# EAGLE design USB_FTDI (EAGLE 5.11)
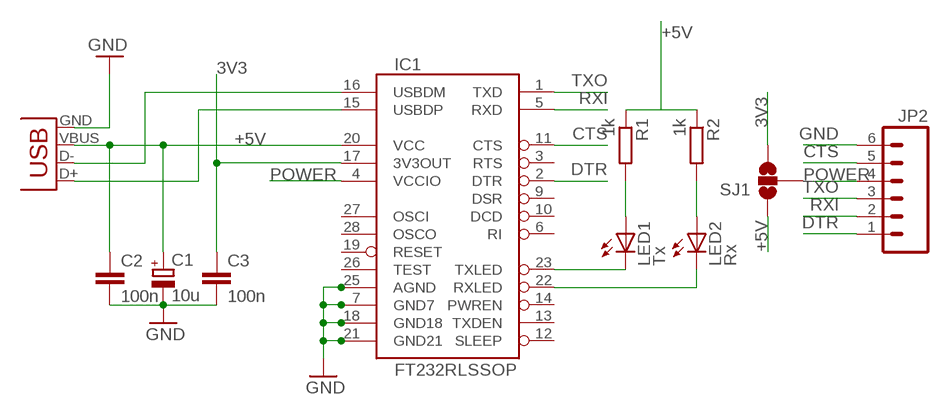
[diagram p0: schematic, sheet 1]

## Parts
C1  10u  CPOL-EUCT6032  [CT6032]
C2  100n  C-EUC0805K  [C0805K]
C3  100n  C-EUC0805K  [C0805K]
IC1  FT232RLSSOP  [SSOP28DB]
JP2  M06SIP  [1X06]
LED1  Tx  LED3MM  [LED3MM]
LED2  Rx  LED3MM  [LED3MM]
R1  1k  R-EU_M0805  [M0805]
R2  1k  R-EU_M0805  [M0805]
SJ1  SOLDERJUMPER_2WAYPASTE2&3  [SJ_3_PASTE2&3]
USB  USB-A-SMD  [USB-A-S-NOSILK-FEMALE]

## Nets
3V3: C3.1 IC1.17(3V3OUT) SJ1.3
+5V: C1.+ C2.1 IC1.20(VCC) R1.1 R2.1 SJ1.1 USB.VBUS
CTS: IC1.11(CTS) JP2.5
DTR: IC1.2(DTR) JP2.1
GND: C1.- C2.2 C3.2 IC1.7(GND7) IC1.18(GND18) IC1.21(GND21) IC1.25(AGND) JP2.6 USB.GND
N$1: LED1.A R1.2
N$2: LED2.A R2.2
N$3: IC1.23(TXLED) LED1.K(C)
N$4: IC1.22(RXLED) LED2.K(C)
N$6: IC1.16(USBDM) USB.D-
N$7: IC1.15(USBDP) USB.D+
POWER: IC1.4(VCCIO) JP2.4 SJ1.2
RXI: IC1.5(RXD) JP2.2
TXO: IC1.1(TXD) JP2.3
Unconnected: IC1.3(RTS) IC1.6(RI) IC1.9(DSR) IC1.10(DCD) IC1.12(SLEEP) IC1.13(TXDEN) IC1.14(PWREN) IC1.19(RESET) IC1.26(TEST) IC1.27(OSCI) IC1.28(OSCO)

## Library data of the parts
C1 = resistor:CPOL-EU: POLARIZED CAPACITOR, European symbol
C2 C3 = rcl:C-EU: CAPACITOR, European symbol
IC1 = SparkFun:FT232RL: USB UART FT232RL 4th Generation USB UART (USB <-> Serial) Controller. Spark Fun Electronics SKU : COM-00650
JP2 = SparkFun:M06: Header 6 Standard 6-pin 0.1" header. Use with straight break away headers (SKU : PRT-00116), right angle break away headers (PRT-00553), swiss pins (PRT-00743), machine pins (PRT-00117), and female headers (PRT-00115). Molex polarized connector foot print use with SKU : PRT-08094 with associated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
LED1 LED2 = led:LED: LED
R1 R2 = resistor:R-EU_: RESISTOR, European symbol
SJ1 = SparkFun:SOLDERJUMPER_2WAY: Solder Jumper 2 way solder jumper
USB = SparkFun:USB: USB Connectors USB-B-PTH is fully proven SKU : PRT-00139 USB-miniB is fully proven SKU : PRT-00587 USB-A-PCB is untested. USB-A-H is throughly reviewed, but untested. Spark Fun Electronics SKU : PRT-00437 USB-B-SMT is throughly reviewed, but untested. Needs silkscreen touching up. USB-A-S has not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

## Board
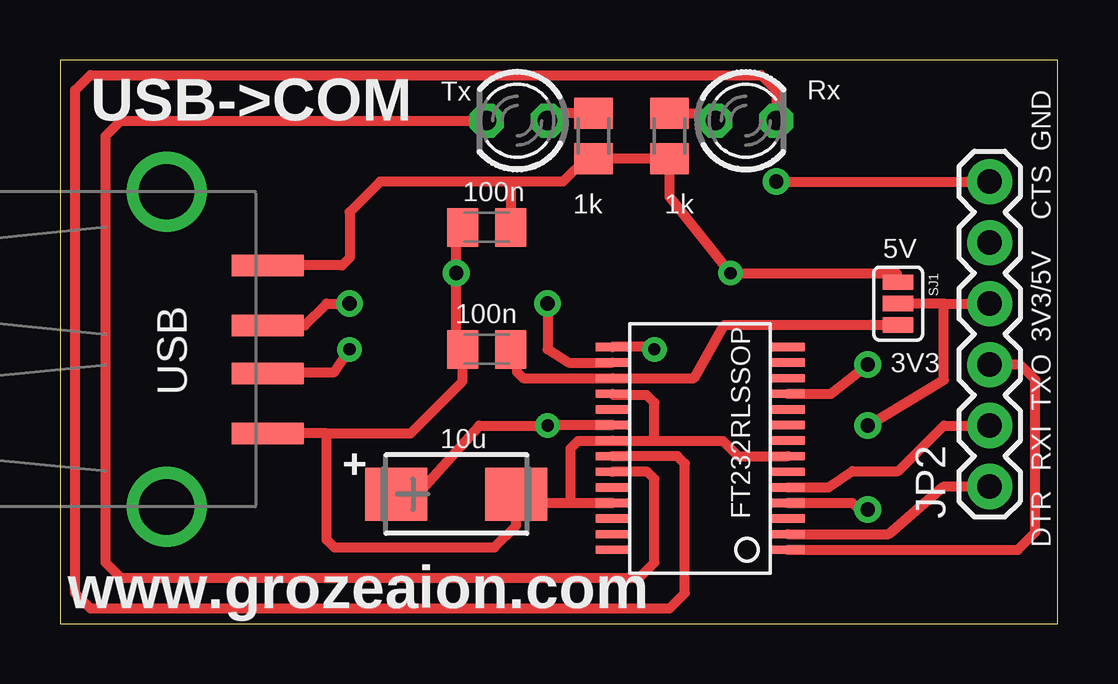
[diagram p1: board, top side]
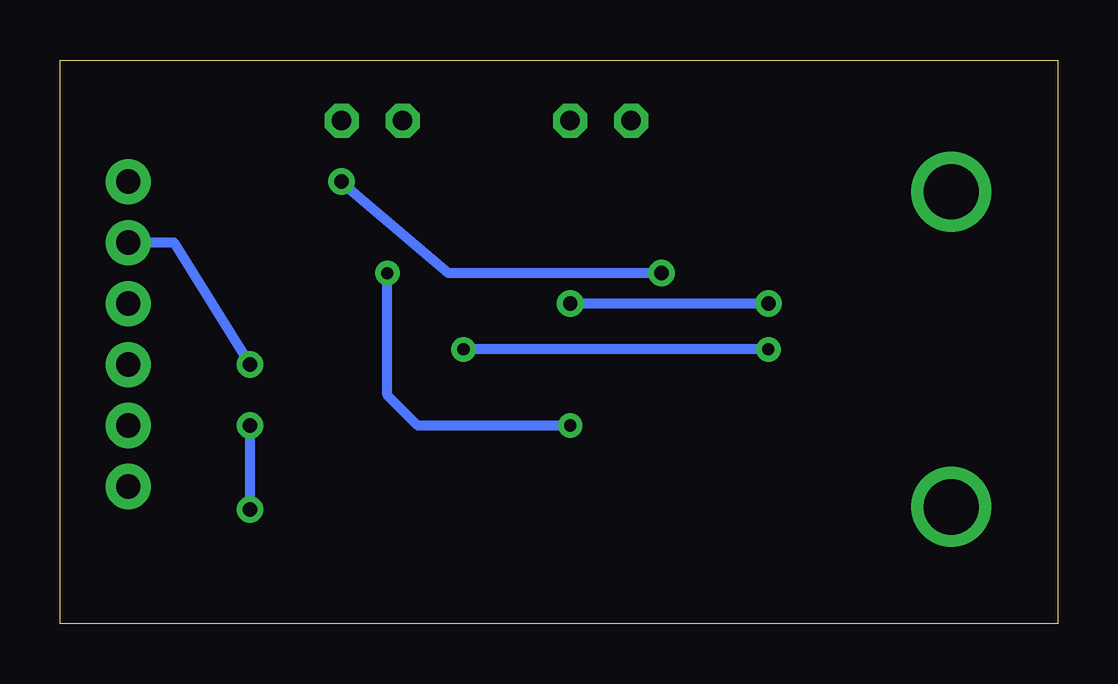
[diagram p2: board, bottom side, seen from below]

Size 41.58 x 23.48 mm. Coordinates in mm from the lower left corner, seen from the top.
Outline: 0,0 41.58,0 41.58,23.48 0,23.48 0,0
Copper layers (1*16): Top 0.035mm / dielectric 1.5mm / Bottom 0.035mm
Design rules "SparkFun": minimum track width 8mil, minimum drill 20mil, track to track 8mil, track to pad 8mil, pad to pad 8mil, via to via 8mil, smd to smd 8mil, copper to edge 10mil, drill to drill 8mil, minimum pad ring 12mil, minimum via ring 10mil, stop-mask expansion 4mil, vias tented up to drill 25mil, thermal gap 10mil

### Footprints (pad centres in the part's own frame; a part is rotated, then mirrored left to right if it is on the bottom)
CT6032 = smd 2.6 x 2.2: + 2.5,0; - -2.5,0
C0805K = smd 1.3 x 1.6: 1 -1,0; 2 1,0
SSOP28DB = smd 0.348 x 1.397: 1 -4.225,-3.656; 2 -3.575,-3.656; 3 -2.925,-3.656; 4 -2.275,-3.656; 5 -1.625,-3.656; 6 -0.975,-3.656; 7 -0.325,-3.656; 8 0.325,-3.656; 9 0.975,-3.656; 10 1.625,-3.656; 11 2.275,-3.656; 12 2.925,-3.656; 13 3.575,-3.656; 14 4.225,-3.656; 15 4.225,3.656; 16 3.575,3.656; 17 2.925,3.656; 18 2.275,3.656; 19 1.625,3.656; 20 0.975,3.656; 21 0.325,3.656; 22 -0.325,3.656; 23 -0.975,3.656; 24 -1.625,3.656; 25 -2.275,3.656; 26 -2.925,3.656; 27 -3.575,3.656; 28 -4.225,3.656
1X06 = drill 1.016 pad 1.88 round: 1 0,0; 2 2.54,0; 3 5.08,0; 4 7.62,0; 5 10.16,0; 6 12.7,0
LED3MM = drill 0.813 octagon: A -1.27,0; K 1.27,0
M0805 = smd 1.3 x 1.6: 1 -0.95,0; 2 0.95,0
SJ_3_PASTE2&3 = smd 0.635 x 1.27: 1 -0.889,0; 2 0,0; 3 0.889,0
USB-A-S-NOSILK-FEMALE = smd 3 x 0.9: D+ 4.212,-1; D- 4.212,1; GND 4.212,-3.5; VBUS 4.212,3.5 | drill 2.311 round: P$5 0,-6.566; P$6 0,6.566

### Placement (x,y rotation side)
C1  16.51,5.4 180 top
C2  17.78,16.51 180 top
C3  17.78,11.43 180 top
IC1  26.67,7.3 90 top
JP2  38.73,5.71 90 top
LED1  19.05,20.95 180 top
LED2  28.57,20.95 0 top
R1  22.23,20.32 90 top
R2  25.4,20.32 90 top
SJ1  34.92,13.34 270 top
USB  4.45,11.43 0 top

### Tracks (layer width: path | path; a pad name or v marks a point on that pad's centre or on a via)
3V3
  Top 0.406: SJ1.3 27.69,12.45 26.42,10.23 IC1.17 19.3,10.23 19.05,10.48 19.05,11.16 C3.1
+5V  (via drill 0.51)
  Top 0.406: USB.VBUS 11.76,14.93 12.06,15.24 12.06,17.14 13.34,18.41 18.73,18.41 | 18.73,18.41 20.95,18.41 21.96,19.42 R1.1 R2.1 25.4,17.78 v27.94,14.61 34.86,14.61 SJ1.1 | IC1.20 20.61,8.28 v20.32,8.26 17.46,8.26 14.61,5.08 C1.+ 14.01,4.49 | C2.1 18.78,18.37 18.73,18.41
  Bottom 0.406: v20.32,8.26 26.67,8.26 27.94,9.53 v27.94,14.61
CTS  (via drill 0.6)
  Top 0.406: IC1.11 32.12,9.58 v33.66,10.79
  Bottom 0.406: v33.66,10.79 36.83,15.88 JP2.5
DTR
  Top 0.406: JP2.1 36.83,5.71 34.52,3.73 IC1.2
GND  (via drill 0.6)
  Top 0.406: 11.11,7.93 USB.GND | 11.11,7.93 14.61,7.93 16.78,10.11 C3.2 16.51,11.7 v16.51,14.61 16.51,16.24 C2.2 | v29.84,18.41 JP2.6 | C1.- 19.27,4.71 | C1.- 19.38,5.03 21.27,5.03 | C1.- 19.01,4.09 18.1,3.17 11.43,3.17 11.11,3.49 11.11,7.93 | 21.27,5.03 IC1.25 | 23.02,7.62 IC1.21 | 23.02,7.62 24.77,7.62 | 24.77,7.62 27.62,7.62 28.27,6.98 IC1.7 | IC1.18 23.07,9.53 24.45,9.53 24.77,9.21 24.77,7.62 | 23.02,7.62 21.59,7.62 21.27,7.3 21.27,5.03
  Bottom 0.406: v29.84,18.41 29.53,18.1 25.4,14.61 v16.51,14.61
N$1
  Top 0.406: R1.2 20.64,21.27 LED1.A
N$2
  Top 0.406: R2.2 26.99,21.27 LED2.A
N$3
  Top 0.406: LED1.K 2.54,20.95 1.91,20.32 1.91,2.54 2.54,1.91 24.13,1.91 24.77,2.54 24.77,6.03 24.47,6.33 IC1.23
N$4
  Top 0.406: LED2.K 29.84,22.23 29.21,22.86 1.27,22.86 0.64,22.23 0.64,1.27 1.27,0.64 25.4,0.64 26.04,1.27 26.04,6.67 25.73,6.98 IC1.22
N$6  (via drill 0.6)
  Top 0.406: v20.32,13.34 20.32,11.43 21.19,10.88 IC1.16 | USB.D- 10.21,12.43 11.11,13.34 v12.06,13.34
  Bottom 0.406: v12.06,13.34 v20.32,13.34
N$7  (via drill 0.51)
  Top 0.406: IC1.15 24.55,11.53 v24.77,11.43 | USB.D+ 8.7,10.48 11.43,10.48 v12.06,11.43
  Bottom 0.406: v12.06,11.43 v24.77,11.43
POWER  (via drill 0.6)
  Top 0.406: 36.83,13.34 SJ1.2 | 36.83,13.34 JP2.4 | IC1.4 33.02,5.03 33.28,4.76 v33.66,4.76 | v33.66,8.26 36.83,10.16 36.83,13.34
  Bottom 0.406: v33.66,4.76 v33.66,8.26
RXI
  Top 0.406: JP2.2 36.83,8.26 34.92,6.35 33.02,6.35 32.03,5.68 IC1.5
TXO
  Top 0.406: IC1.1 39.91,3.08 40.64,3.81 40.64,10.16 40.01,10.79 JP2.3

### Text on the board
tPlace: USB->COM | GND | CTS | 5V | 3V3/5V | 3V3 | TXO | + | RXI | DTR | www.grozeaion.com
